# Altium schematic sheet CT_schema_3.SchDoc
size 591 x 347 mm
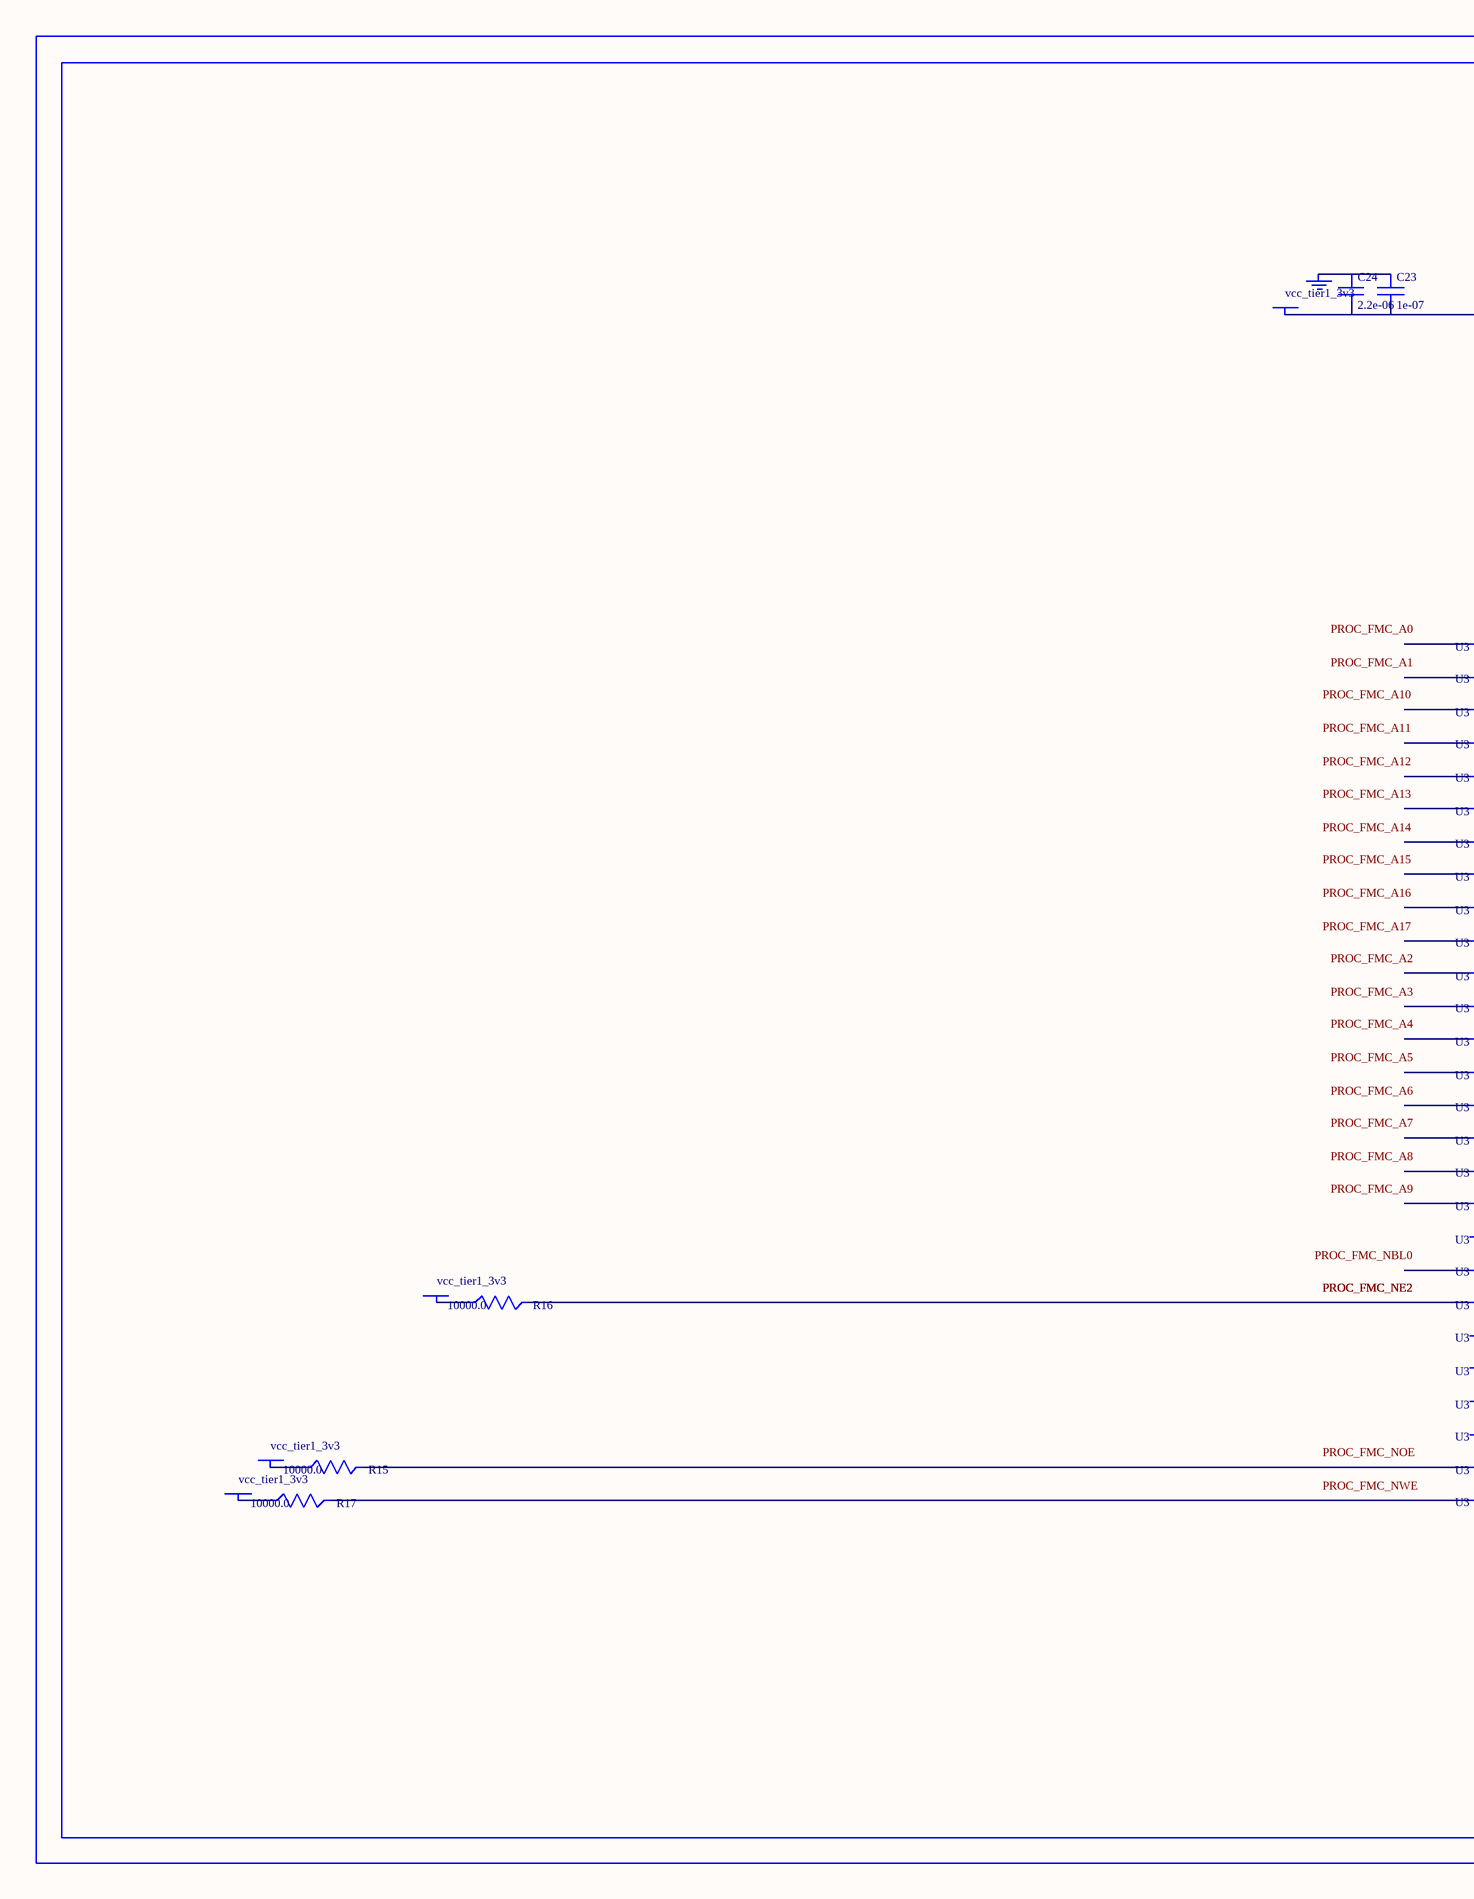
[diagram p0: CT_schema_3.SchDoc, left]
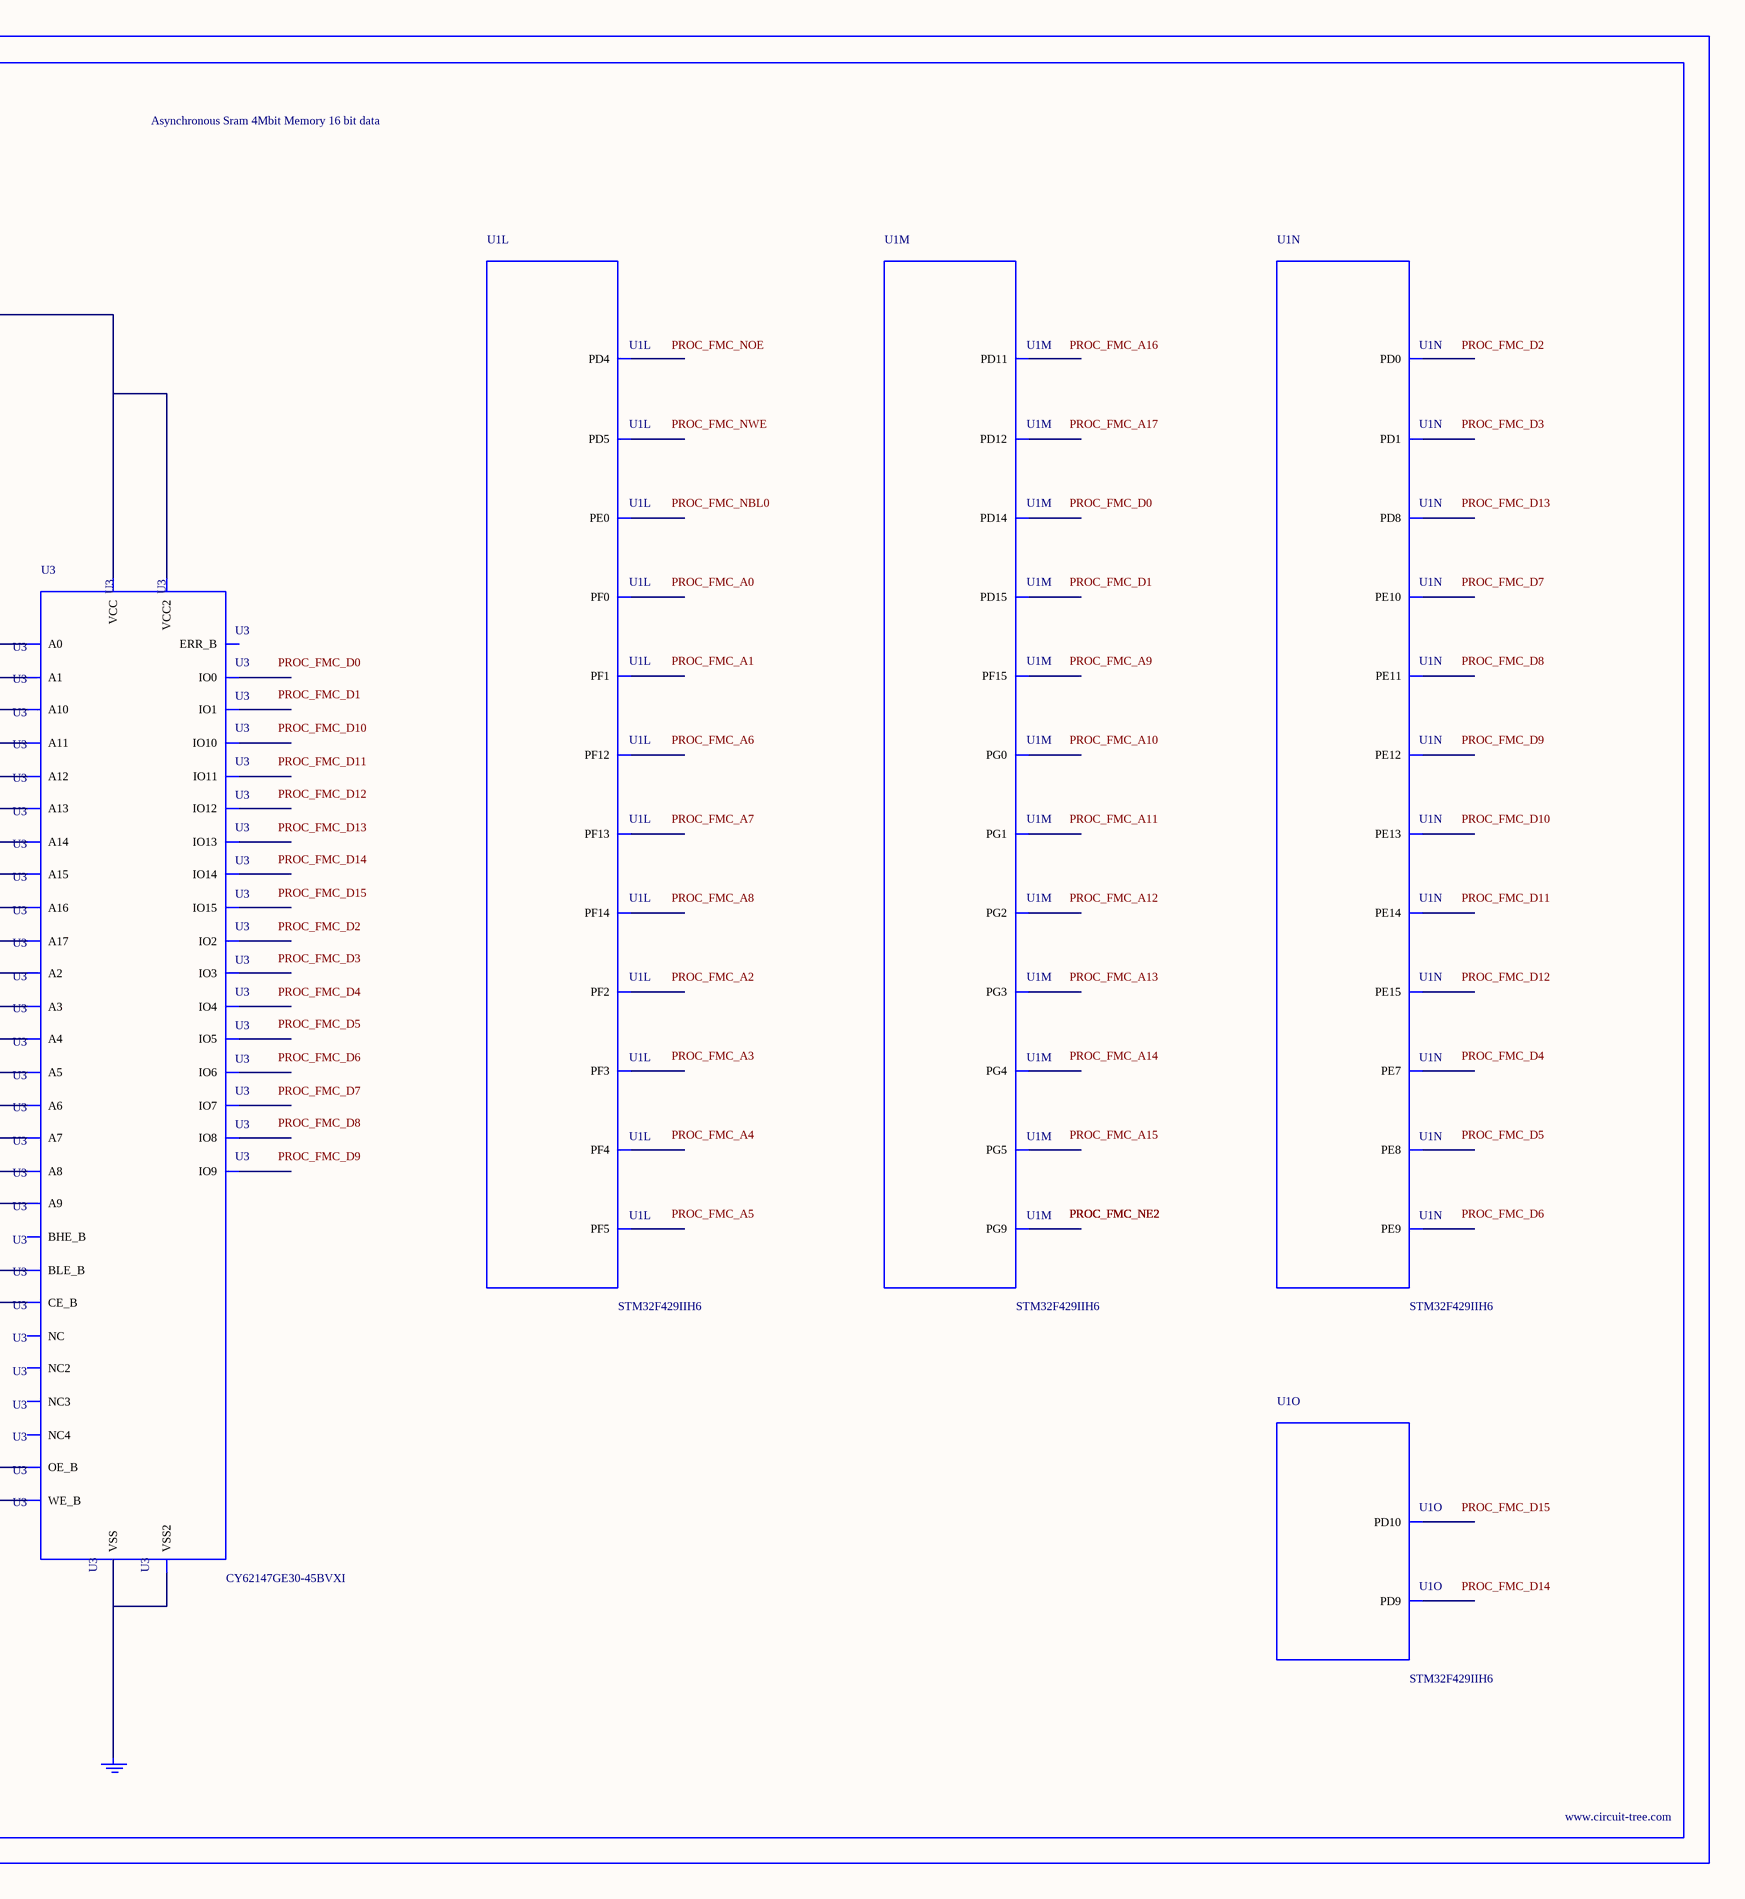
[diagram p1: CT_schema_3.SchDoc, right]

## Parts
BORDER2  (no value)
C23  1e-07  [C0402]
C24  2.2e-06  [C0603]
GND_INSTANCE_2_0  (no value)
GND_INSTANCE_2_1  (no value)
POWER_INSTANCE_2_0  vcc_tier1_3v3
POWER_INSTANCE_2_1  vcc_tier1_3v3
POWER_INSTANCE_2_2  vcc_tier1_3v3
POWER_INSTANCE_2_3  vcc_tier1_3v3
R15  10000.0  [R0603]
R16  10000.0  [R0603]
R17  10000.0  [R0603]
U1  STM32F429IIH6  [UFBGA176_25]  (parts L,M,N,O of 16)
U3  CY62147GE30-45BVXI  [VFBGA48]

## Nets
NetC23_1: C23.1 C24.1 GND_INSTANCE_2_0.0(GND)
NetC23_2: C23.2 C24.2 POWER_INSTANCE_2_0.0(PWR) U3.D6(VCC) U3.E1(VCC2)
NetGND_INSTANCE_2_1_0: GND_INSTANCE_2_1.0(GND) U3.D1(VSS) U3.E6(VSS2)
NetPOWER_INSTANCE_2_1_0: POWER_INSTANCE_2_1.0(PWR) R15.1
NetPOWER_INSTANCE_2_2_0: POWER_INSTANCE_2_2.0(PWR) R16.1
NetPOWER_INSTANCE_2_3_0: POWER_INSTANCE_2_3.0(PWR) R17.1
NetR15_2: R15.2 U3.A2(OE_B)
NetR16_2: R16.2 U3.B5(CE_B)
NetR17_2: R17.2 U3.G5(WE_B)

Not connected (* = marked no-connect by the designer): U1 A4(PE0) B12(PD0) C10(PG9) C11(PD5) C12(PD1) D10(PD4) E2(PF0) H2(PF2) H3(PF1) J2(PF3) J3(PF4) K3(PF5) K13(PG5) K14(PG4) K15(PG3) L14(PD15) L15(PG2) M7(PG1) M14(PD14) N6(PF13) N7(PG0) N11(PE13) N13(PD12) N14(PD11) N15(PD10) P6(PF12) P7(PF15) P8(PE8) P9(PE9) P10(PE11) P11(PE14) P14(PD9) P15(PD8) R7(PF14) R8(PE7) R9(PE10) R10(PE12) R11(PE15); U3 A1(BLE_B) A3(A0) A4(A1) A5(A2) A6(NC) B1(IO8) B2(BHE_B) B3(A3) B4(A4) B6(IO0) C1(IO9) C2(IO10) C3(A5) C4(A6) C5(IO1) C6(IO2) D2(IO11) D3(A17) D4(A7) D5(IO3) E2(IO12) E3(ERR_B) E4(A16) E5(IO4) F1(IO14) F2(IO13) F3(A14) F4(A15) F5(IO5) F6(IO6) G1(IO15) G2(NC2) G3(A12) G4(A13) G6(IO7) H1(NC3) H2(A8) H3(A9) H4(A10) H5(A11) H6(NC4)

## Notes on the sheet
- Labels drawn without touching a wire or pin: PROC_FMC_A0, PROC_FMC_A1, PROC_FMC_A2, PROC_FMC_A3, PROC_FMC_A4, PROC_FMC_A5, PROC_FMC_A6, PROC_FMC_A7, PROC_FMC_A8, PROC_FMC_A9, PROC_FMC_A10, PROC_FMC_A11, PROC_FMC_A12, PROC_FMC_A13, PROC_FMC_A14, PROC_FMC_A15, PROC_FMC_A16, PROC_FMC_A17, PROC_FMC_D0, PROC_FMC_D1, PROC_FMC_D2, PROC_FMC_D3, PROC_FMC_D4, PROC_FMC_D5, PROC_FMC_D6, PROC_FMC_D7, PROC_FMC_D8, PROC_FMC_D9, PROC_FMC_D10, PROC_FMC_D11, PROC_FMC_D12, PROC_FMC_D13, PROC_FMC_D14, PROC_FMC_D15, PROC_FMC_NBL0, PROC_FMC_NOE, PROC_FMC_NWE

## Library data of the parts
BORDER2 = BORDER_PAGE2
C23 = C0402C104K3RACTU
C24 = C0603C225K8RACTU
GND_INSTANCE_2_0 GND_INSTANCE_2_1 = GND
POWER_INSTANCE_2_0-POWER_INSTANCE_2_3 = PWR
R15-R17 = RC0603JR-0710KL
